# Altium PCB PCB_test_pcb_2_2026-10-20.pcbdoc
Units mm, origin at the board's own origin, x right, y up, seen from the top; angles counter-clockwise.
Board outline 59.65 x 48.65 mm, 2 copper layers (Top Layer, Bottom Layer); 8 components, 5 nets, 17 pads, 0 vias.
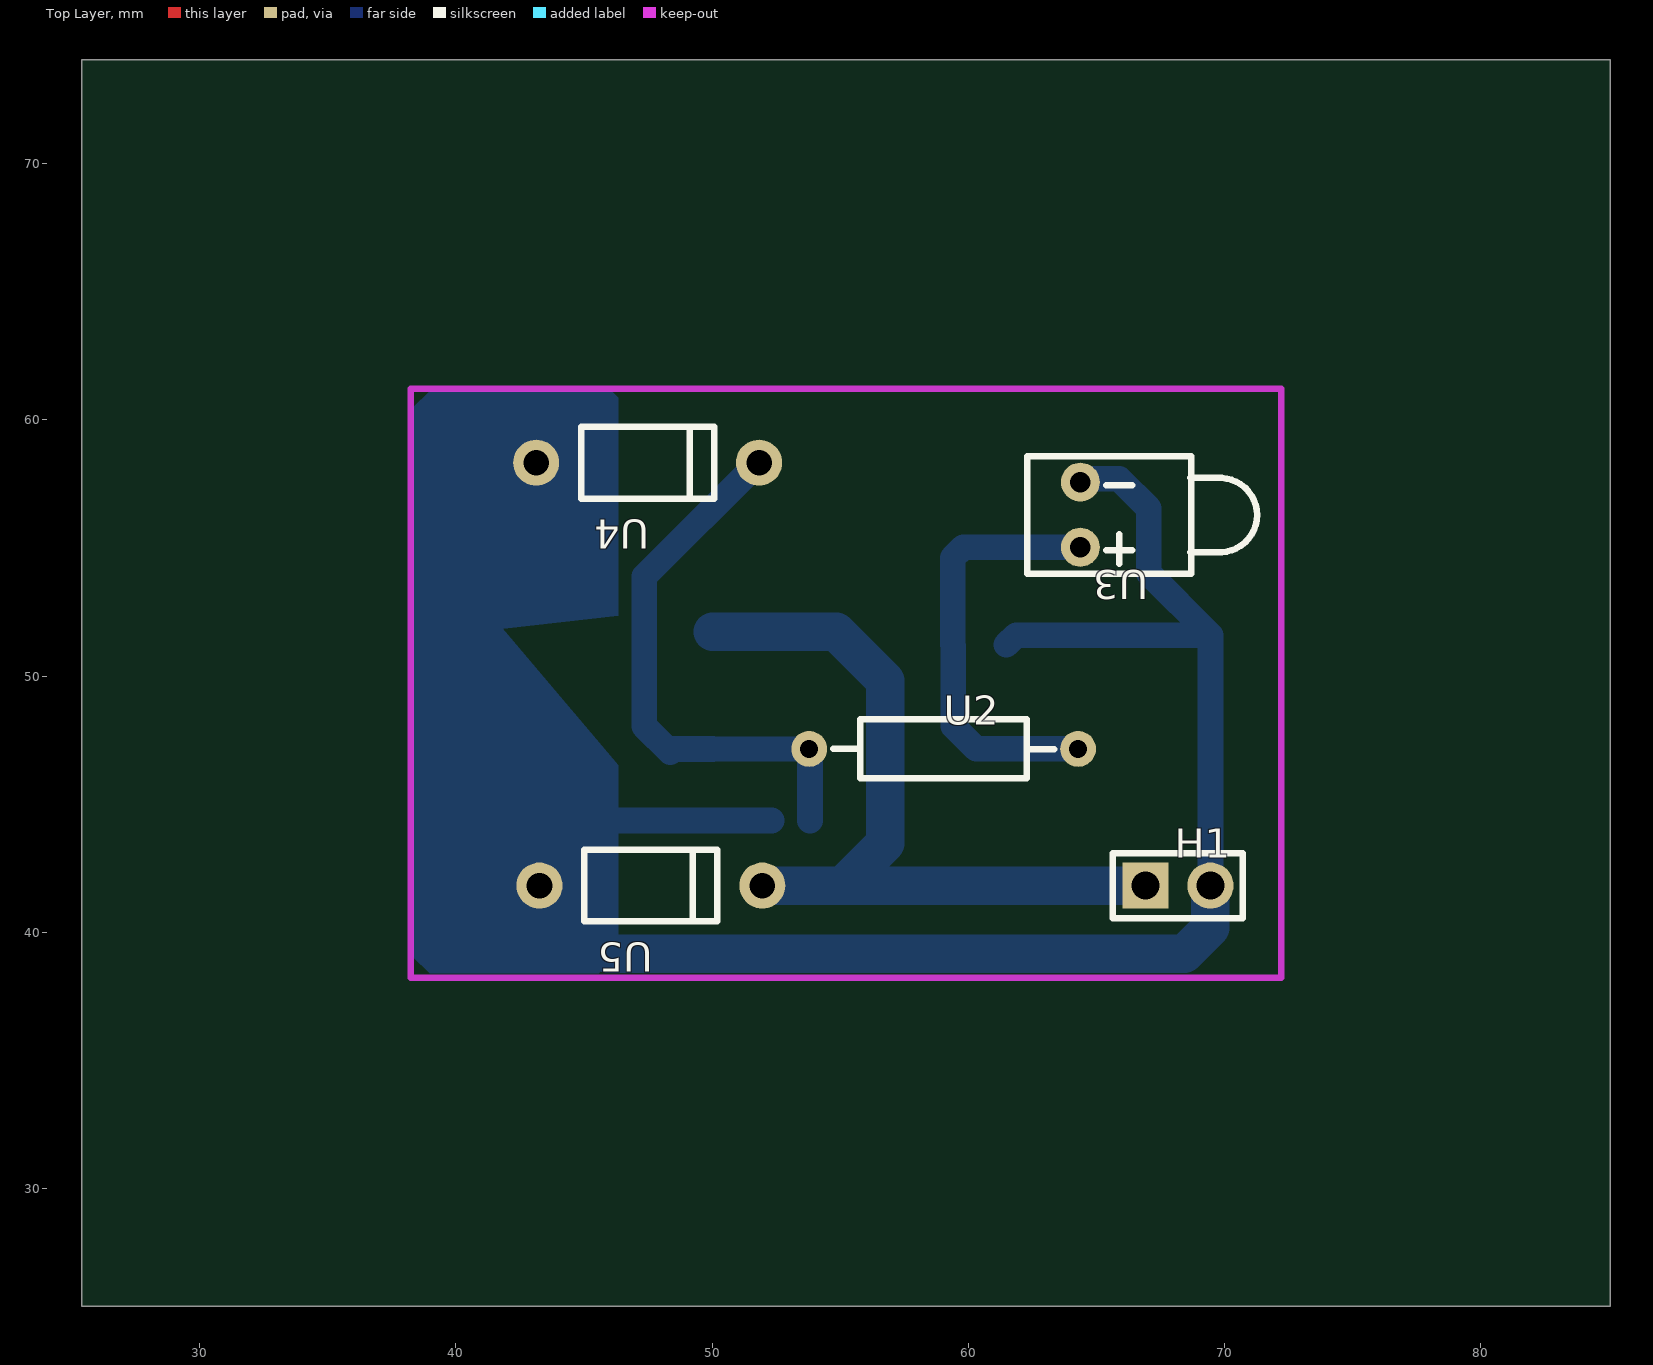
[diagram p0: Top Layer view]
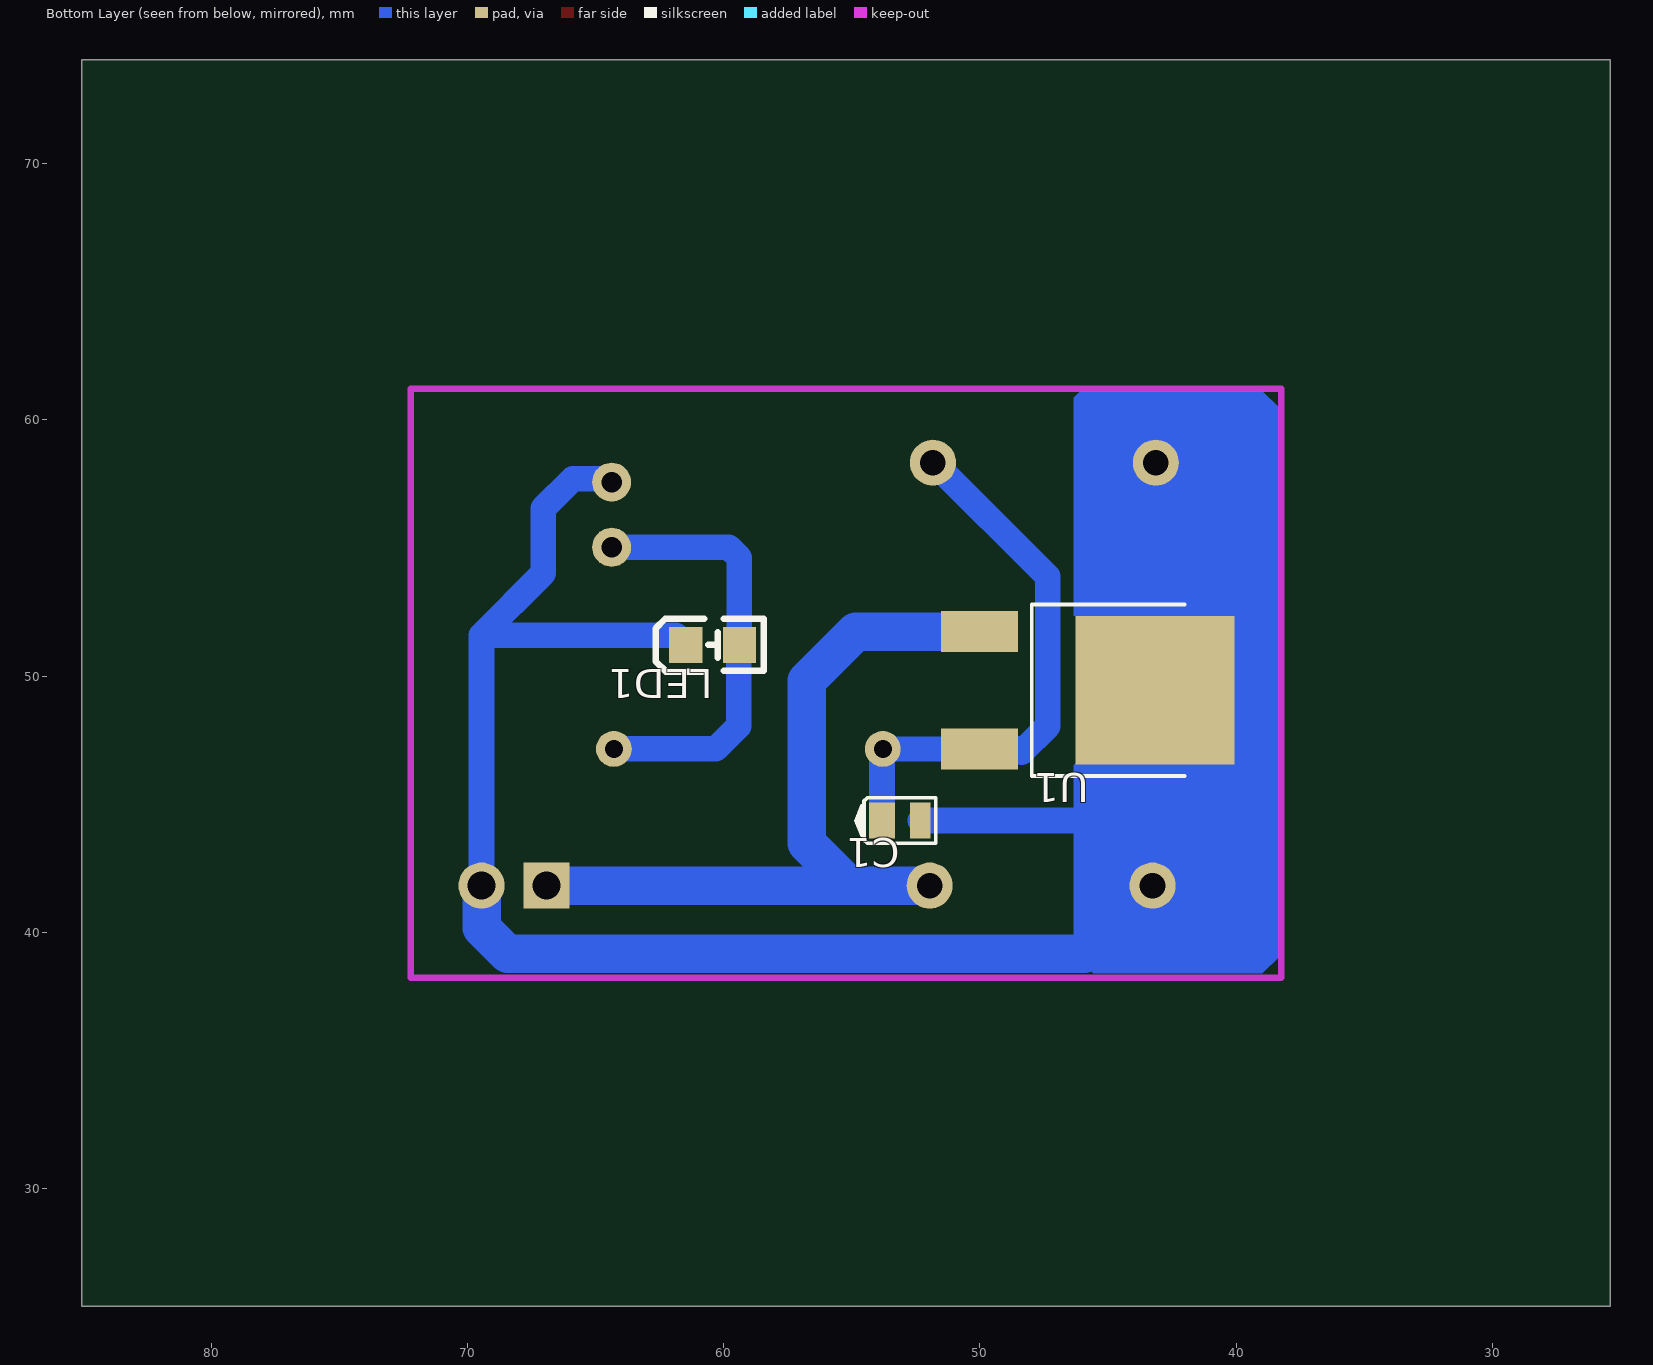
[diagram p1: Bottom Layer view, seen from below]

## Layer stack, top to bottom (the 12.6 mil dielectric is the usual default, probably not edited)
Top Layer: signal copper (thickness not stored)
Dielectric: dielectric 0.32, FR-4, Dk 4.8
Bottom Layer: signal copper (thickness not stored)

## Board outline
85.054,25.4 25.4,25.4 25.4,74.054 85.054,74.054

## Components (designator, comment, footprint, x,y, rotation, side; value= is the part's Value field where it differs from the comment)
C1 "100nF" CAP-SMD_L2.2-W1.3-RD 53.071,44.363 r180 bottom
H1 "210S-1*2P L=11.6MMGold-plated black" HDR-TH_2P-P2.54-V-M-1 68.184,41.823 r0 top
LED1 "YLED0805O" LED0805-FD-GREEN 60.437,51.221 r180 bottom
U1 "7805_C19626525" TO-252-2_L6.6-W6.1-P4.57-LS9.9-BR-CW 46.594,49.443 r180 bottom
U2 "330mΩ" RES-TH_BD2.3-L6.5-P10.50-D0.5 59.04,47.157 r0 top
U3 "LED05-红灯" LED-TH_LED-3MM_RED 64.374,56.301 r180 top
U4 "1N4007A" DO-41_BD2.4-L4.7-P8.70-D0.9-RD 47.483,58.333 r180 top
U5 "1N4007A" DO-41_BD2.4-L4.7-P8.70-D0.9-RD 47.61,41.823 r180 top

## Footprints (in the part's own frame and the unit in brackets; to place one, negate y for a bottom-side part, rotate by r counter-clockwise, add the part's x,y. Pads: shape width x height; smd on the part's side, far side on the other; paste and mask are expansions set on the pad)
CAP-SMD_L2.2-W1.3-RD [mm]
  rect 0.8x1.4 smd paste+0 mask+0.05: 1(0.75,0)
  rect 1x1.4 smd paste+0 mask+0.05: 2(-0.75,0)
  silkscreen extent -1.83,-0.89 1.35,0.89
DO-41_BD2.4-L4.7-P8.70-D0.9-RD [mm]
  round 1.8 hole 1 paste+0 mask+0.051: 1(-4.35,0) 2(4.35,0)
  silkscreen extent -2.6,-1.4 2.6,1.4
HDR-TH_2P-P2.54-V-M-1 [mm]
  rect 1.8x1.8 hole 1.1 paste+0 mask+0.051: 1(-1.27,0)
  round 1.8 hole 1.1 paste+0 mask+0.051: 2(1.27,0)
  silkscreen extent -2.54,-1.27 2.54,1.27
LED0805-FD-GREEN [mm]
  rect 1.3x1.4 smd paste+0 mask+0.051: 1(1.05,0) 2(-1.05,0)
  silkscreen extent -2.22,-1.04 1.99,1.01
LED-TH_LED-3MM_RED [mil]
  round 60 hole 31.5 paste+0 mask+1.97: 1(0,50) 2(0,-50)
  silkscreen extent -272,-90 82,91
RES-TH_BD2.3-L6.5-P10.50-D0.5 [mm]
  round 1.4 hole 0.7 paste+0 mask+0.051: 1(-5.25,0) 2(5.25,0)
  silkscreen extent -4.32,-1.15 4.32,1.15
TO-252-2_L6.6-W6.1-P4.57-LS9.9-BR-CW [mm]
  rect 3x1.6 smd paste+0 mask+0.051: 1(-3.424,2.29) 3(-3.424,-2.29)
  rect 6.2x5.8 smd paste+0 mask+0.051: 2(3.424,0)
  silkscreen extent -1.38,-3.35 4.58,3.35

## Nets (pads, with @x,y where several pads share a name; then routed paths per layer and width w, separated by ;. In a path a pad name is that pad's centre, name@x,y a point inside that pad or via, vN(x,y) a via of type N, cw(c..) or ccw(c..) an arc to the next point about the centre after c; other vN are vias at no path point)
5V: C1.2 U1.3 U2.1 U4.1 | length 21.9
  Bottom Layer w1: U4.1 51.801,58.333 47.356,53.888 47.356,48.046 48.372,47.03 48.495,47.153 U1.3 U2.1 53.821,47.126 C1.2
12V: H1.1 U1.1 U5.1 | length 34.3
  Bottom Layer w1.5: U1.1@50.018,51.734 54.844,51.734 56.754,49.824 56.754,43.474 55.103,41.823 U5.1 ; U5.1 H1.1
GND: C1.1 H1.2 LED1.2 U1.2 U3.2 U4.2 U5.2 | length 66.5
  Bottom Layer w1: U5.2@43.26,41.823 45.8,44.363 C1.1 ; LED1.2 61.868,51.602 69.454,51.602 ; U3.2 64.501,57.698 65.898,57.698 67.041,56.555 67.041,54.015 69.454,51.602 ; H1.2 69.454,51.602
  Bottom Layer w1.5: U5.2 45.926,39.156 68.438,39.156 69.454,40.172 H1.2
LED1_1: LED1.1 U2.2 U3.1 | length 17
  Bottom Layer w1: LED1.1 59.387,54.616 59.802,55.031 U3.1 ; LED1.1 59.421,51.186 59.421,48.046 60.31,47.157 U2.2
U1_2:  | length 5.5
  Bottom Layer w1.5: 43.8,39.537 43.26,40.077 43.26,41.823 43.26,40.712 44.562,39.41

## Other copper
Bottom Layer:
  region net GND: 46.34,52.364 46.34,60.873 46.086,61.127 38.974,61.127 38.339,60.492 38.339,51.348 39.355,51.348 39.609,51.602
  region net GND: 46.34,46.522 46.34,39.156 45.578,38.394 38.974,38.394 38.339,39.029 38.339,54.015 39.228,54.904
